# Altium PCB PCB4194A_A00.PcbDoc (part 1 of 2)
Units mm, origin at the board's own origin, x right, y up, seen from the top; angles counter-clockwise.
Board outline 30 x 45 mm, 4 copper layers (Top Layer, Signal Layer 2, Signal Layer 3, Bottom Layer), stack 1.6 mm thick; 81 components, 86 nets, 293 pads, 429 vias.
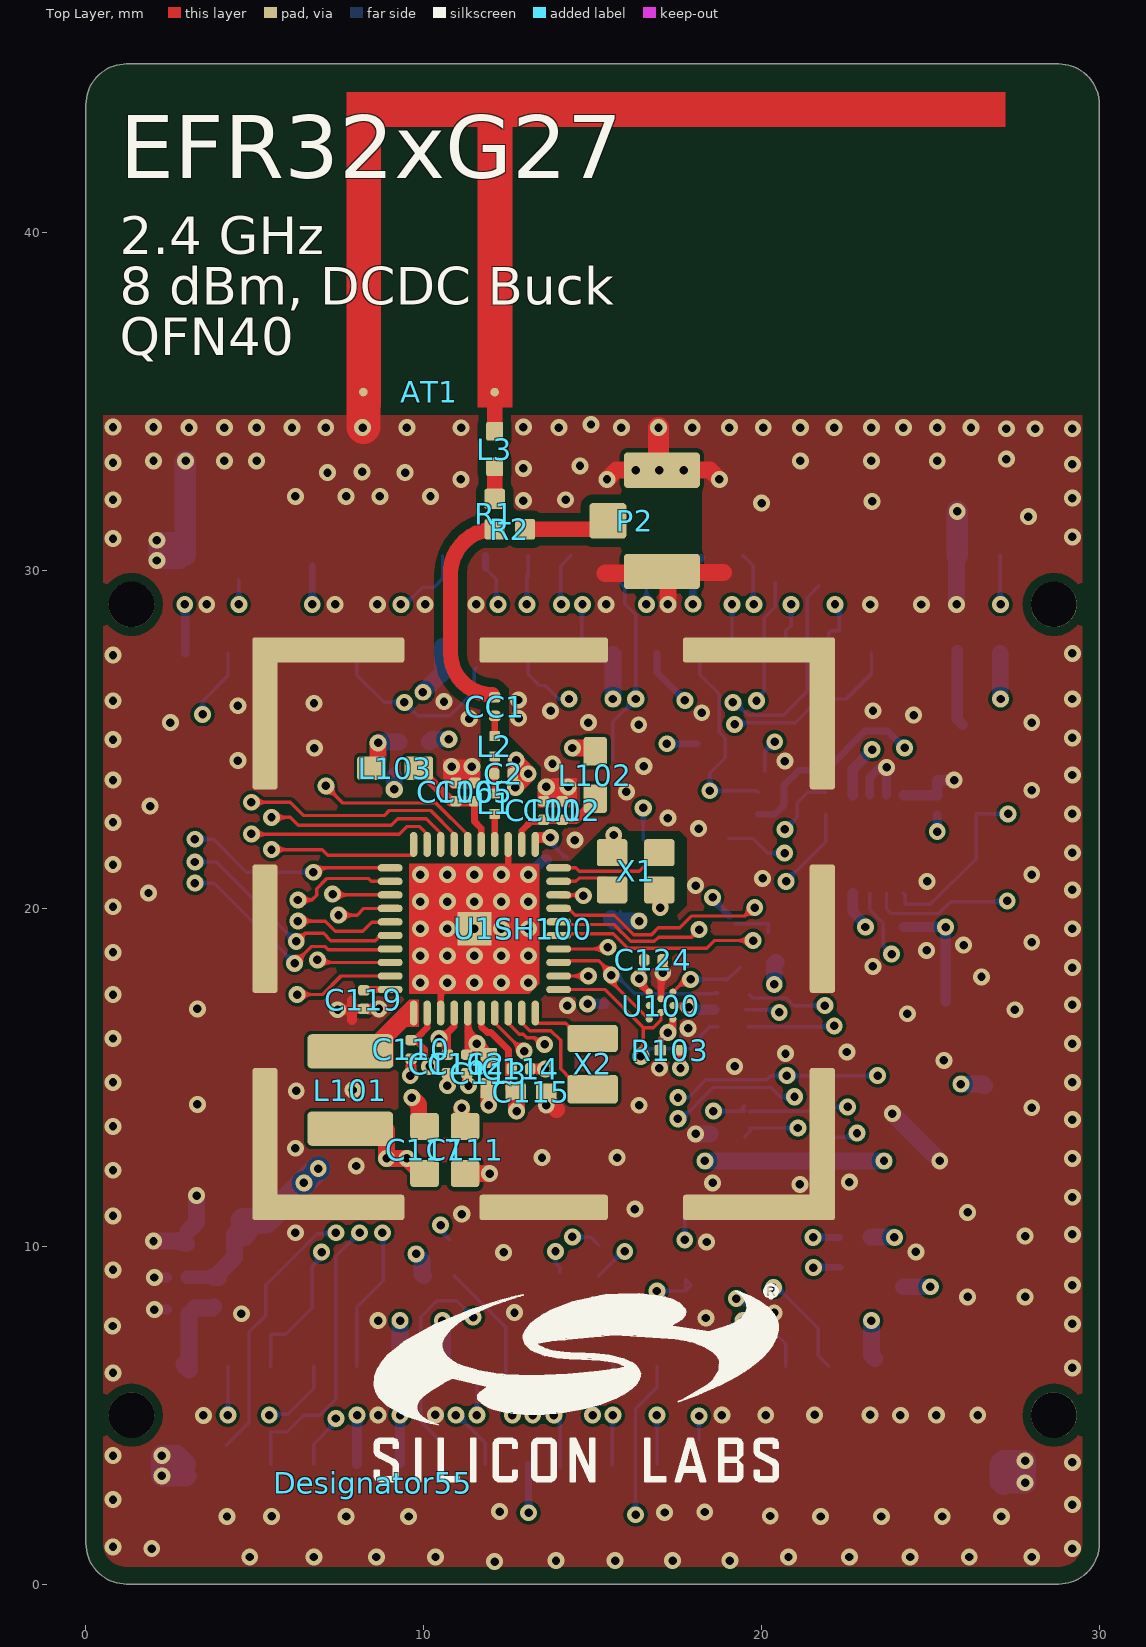
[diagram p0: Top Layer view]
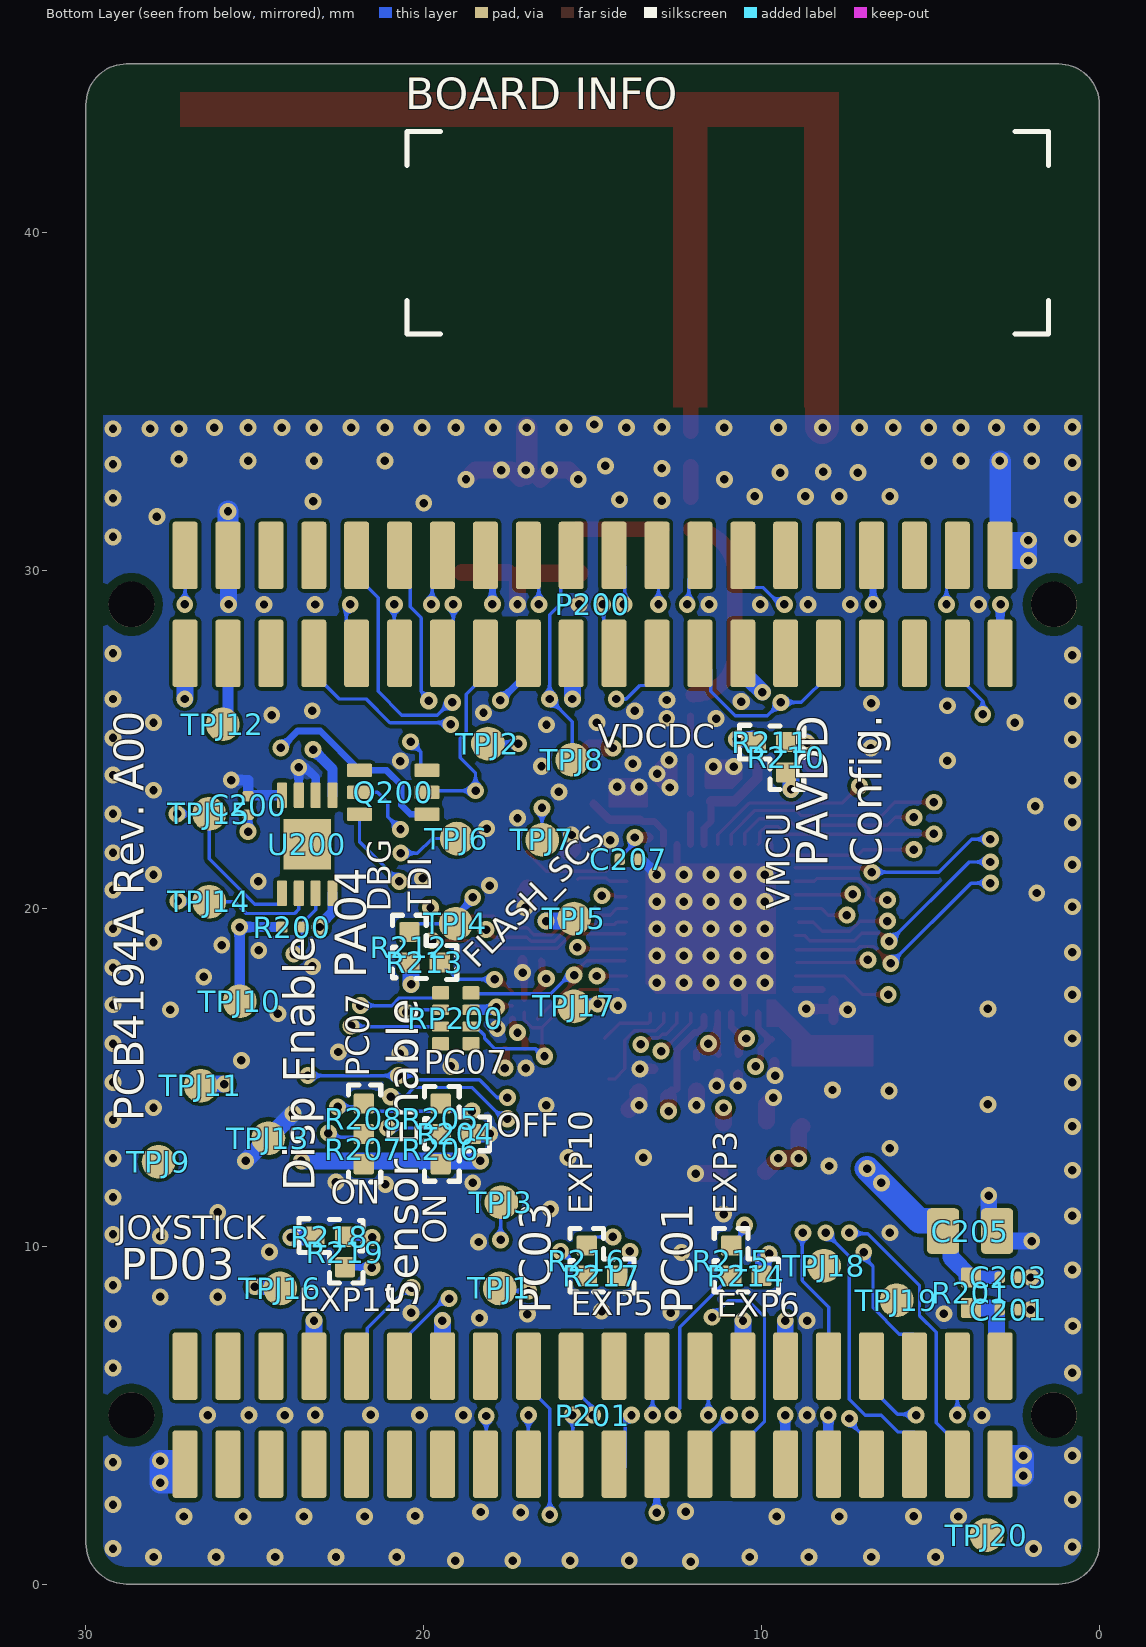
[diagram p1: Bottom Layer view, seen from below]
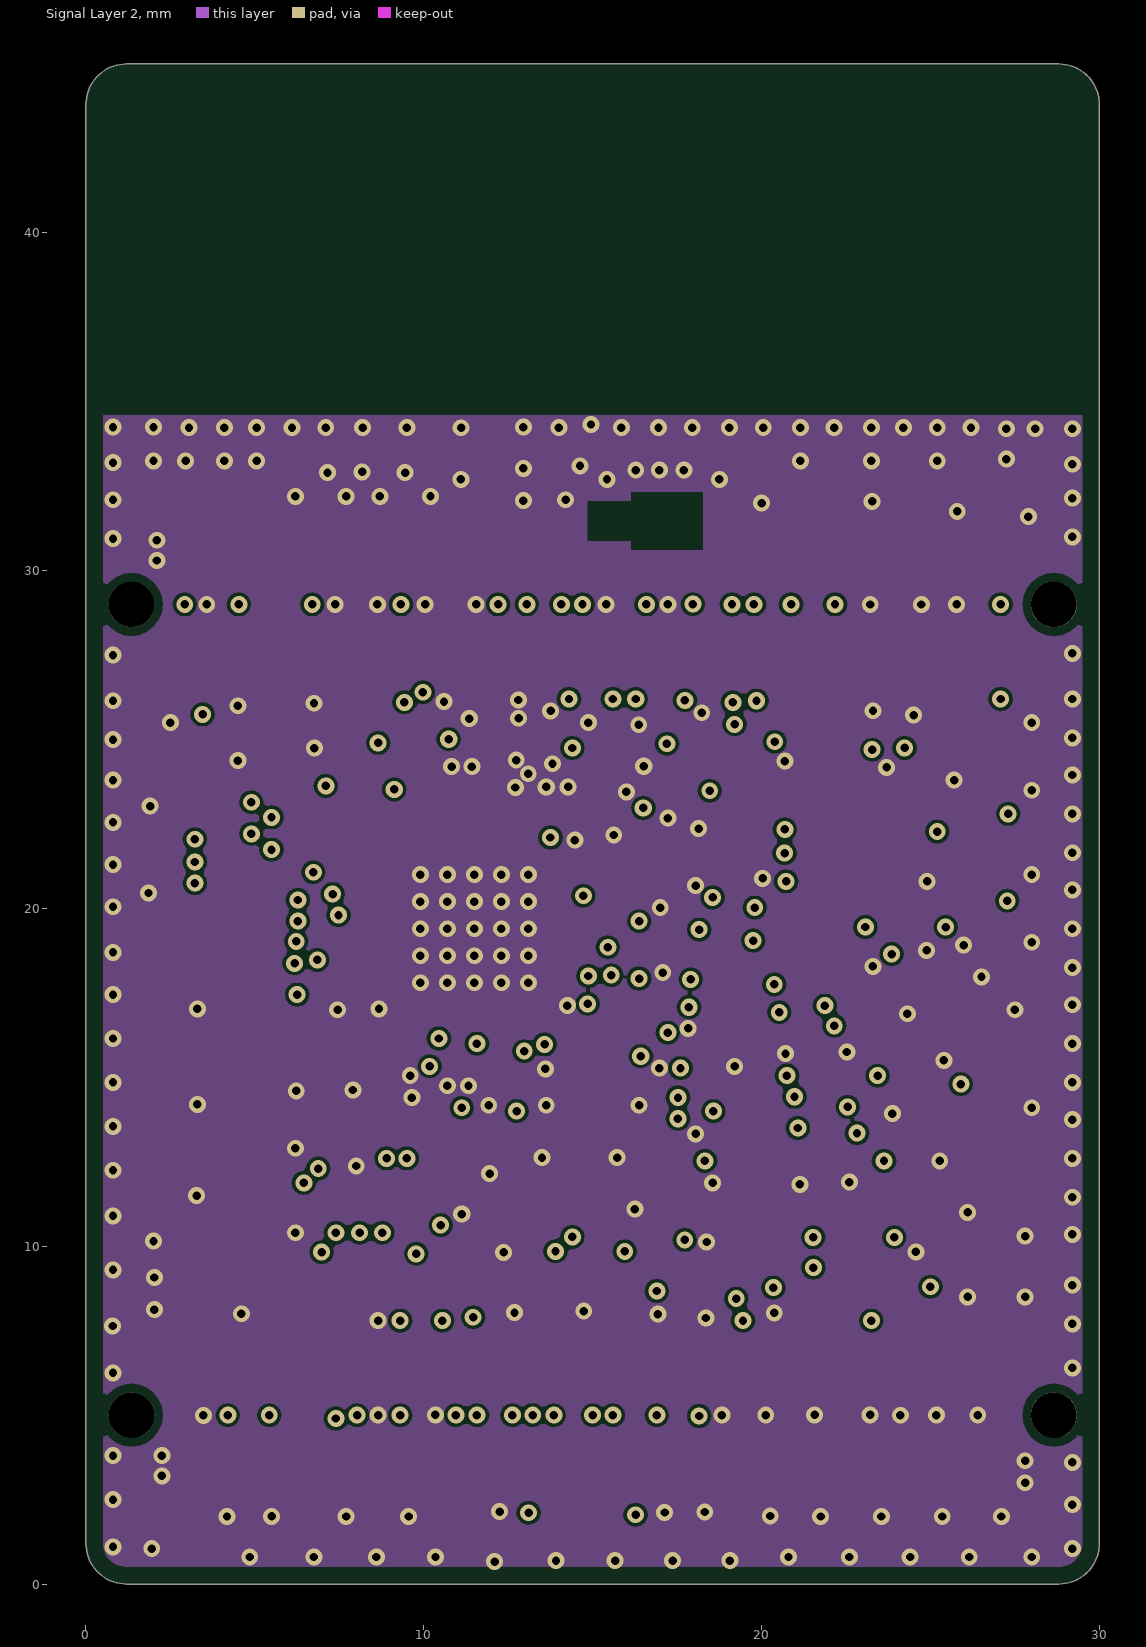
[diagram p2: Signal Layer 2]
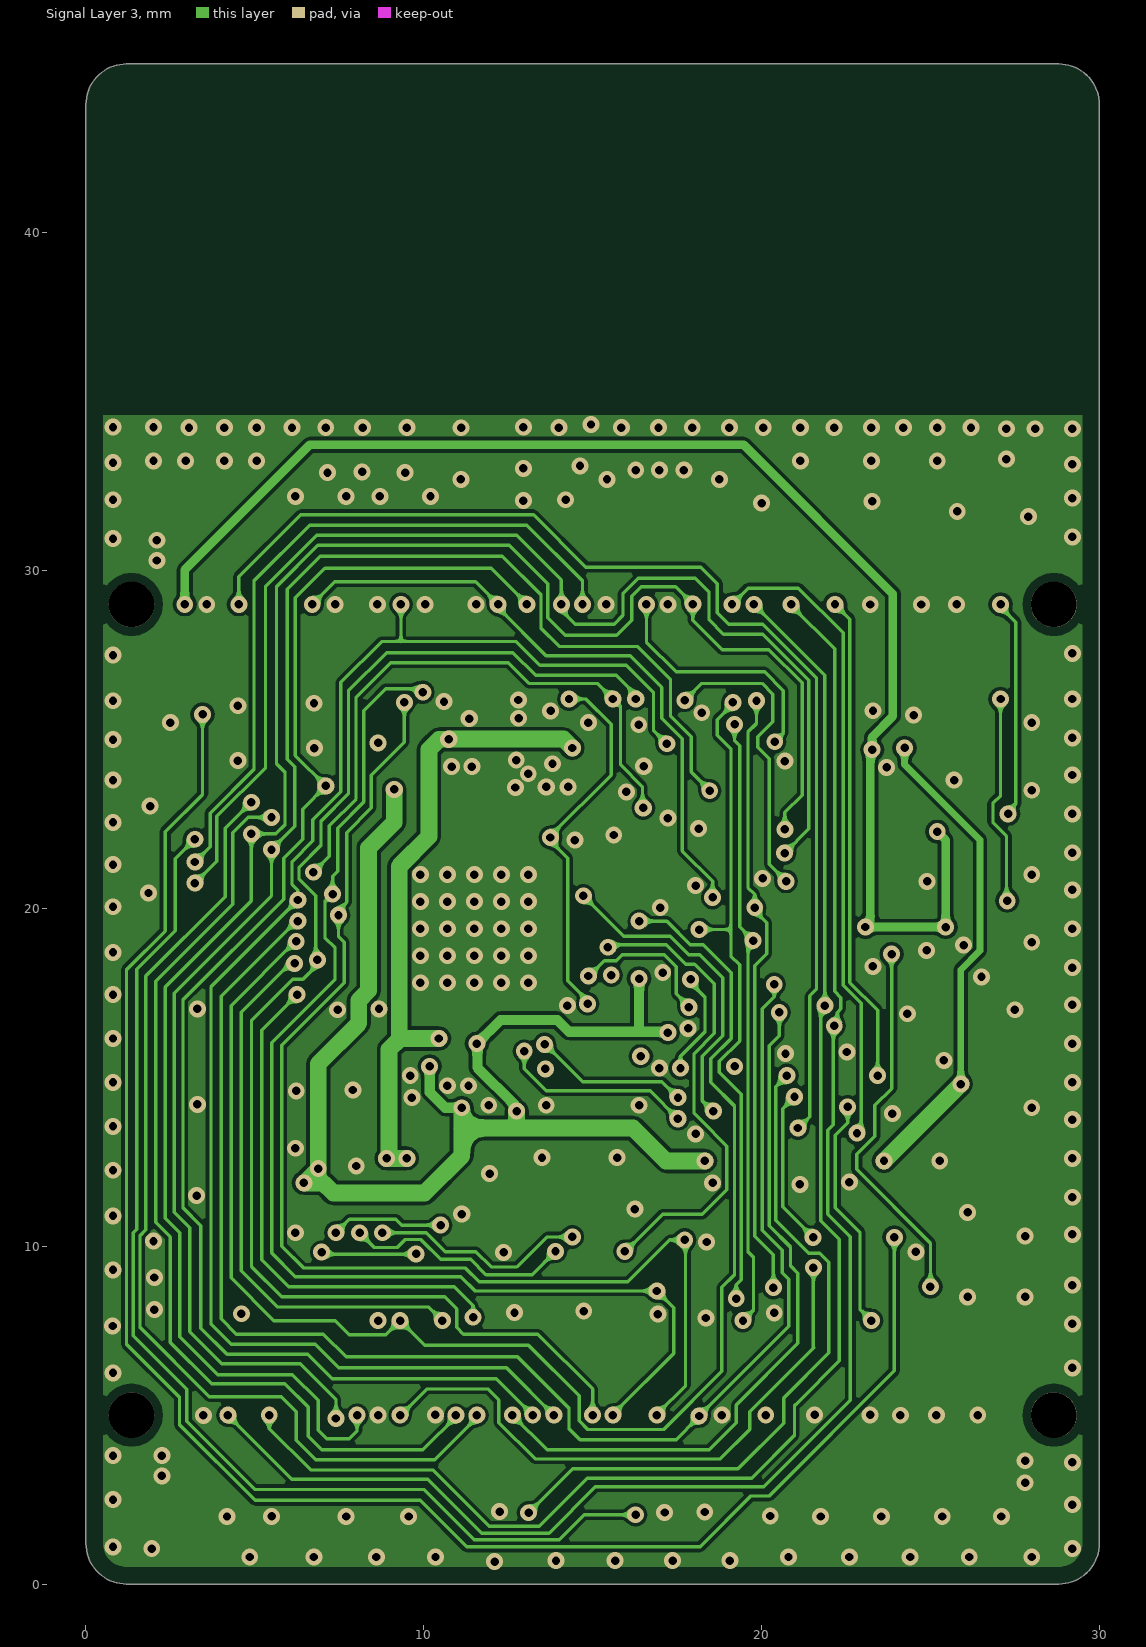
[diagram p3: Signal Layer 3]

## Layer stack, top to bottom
Top Solder: solder mask 0.0102, Solder Resist, Dk 3.5
Top Layer: signal copper 0.035
Dielectric 1: core 0.325, FR-4, Dk 4.2
Signal Layer 2: signal copper 0.018
Dielectric 3: prepreg 0.844, Dk 4.2
Signal Layer 3: signal copper 0.018
Dielectric 2: core 0.325, Dk 4.2
Bottom Layer: signal copper 0.035
Bottom Solder: solder mask 0.0102, Solder Resist, Dk 3.5

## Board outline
0,1.2 0,43.8 cw(c1.2,43.8) 1.2,45 28.8,45 cw(c28.8,43.8) 30,43.8 30,1.2 cw(c28.8,1.2) 28.8,0 1.2,0 cw(c1.2,1.2)

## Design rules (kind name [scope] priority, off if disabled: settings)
AcuteAngle [All] p1: minimum=7.00000000000000E+0001 checktracksonly=FALSE
BoardOutlineClearance [All] p1: gap=0.5
Clearance Clearance_50Ohm [InNet('50R*') vs InNet('GND')] p1: gap=0.254 except(0.15: Track-SMDPad; 0.2: SMDPad-SMDPad)
Clearance Clearance_to_Holes [InPadClass('NPTH')] p2: gap=0.254
Clearance Clerance_Polygon [InPolygon] p3: gap=0.1
Clearance Clearance_General [All] p4: gap=0.1
HoleToHoleClearance HoleToHoleClearance_ANT1toPAD [Incomponent ('ANT1') vs ISpad] p1: gap=0 allowstackedmicrovias=TRUE
HoleToHoleClearance HoleToHoleClearance_R1toR2_1 [Incomponent ('R1') vs Incomponent ('R2')] p2: gap=0 allowstackedmicrovias=TRUE
HoleToHoleClearance HoleToHoleClearance_U1toVIA_1 [InComponent ('U1') vs IsVia] p3: gap=0 allowstackedmicrovias=TRUE
HoleToHoleClearance [All] p4: gap=0.254 allowstackedmicrovias=TRUE
MinimumSolderMaskSliver [All] p1: minsoldermaskwidth=0.075
PolygonConnect Polygon_VIA_Connect [IsVia] p1: connectstyle=Direct reliefconductorwidth=0.254 reliefentries=4 polygonreliefangle="90 Angle" airgapwidth=0.254
PolygonConnect PolygonConnect_SH100 [InComponent('SH100')] p2: connectstyle=Direct reliefconductorwidth=0.254 reliefentries=4 polygonreliefangle="90 Angle" airgapwidth=0.127
PolygonConnect [All] p3: connectstyle=NoConnect reliefconductorwidth=0.254 reliefentries=4 polygonreliefangle="90 Angle" airgapwidth=0.127
RoutingVias [All] p1: holewidth=0.3 width=0.65 viastyle="Through Hole" minholewidth=0.25 minwidth=0.5 maxholewidth=1 maxwidth=1.5
ShortCircuit ShortCircuit_ANTtoPAD [InNet('NetAT1_1') vs InNet('GND')] p1: allowed=TRUE
ShortCircuit ShortCircuit_R1toR2_1 [Incomponent ('R1') vs Incomponent ('R2')] p2: allowed=TRUE
ShortCircuit [All] p3: allowed=FALSE
SilkToSilkClearance [All] p1: silktosilkclearance=0.102
SilkToSolderMaskClearance [IsPad] p1: minsilkscreentomaskgap=0.102 clearancetoexposedcopper=TRUE
SolderMaskExpansion [All] p1: expansion=0.051
Width 50ohm [InNet('50R*')] p1: maxlimit=0.457 minlimit=0.2 preferedwidth=0.457
Width [All] p2: maxlimit=5.08 minlimit=0.1 preferedwidth=0.125
25 further rules are at their usual default settings.

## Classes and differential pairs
pad class NPTH: P200-M1 P200-M2 P201-M1 P201-M2

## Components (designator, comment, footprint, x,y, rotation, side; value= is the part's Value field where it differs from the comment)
AT1 "INVERTED_F" EM358x_INVERTED_F 7.714,34.835 r0 top net-tie
C2 "1P3" C0201_L 12.361,23.983 r0 top
C101 "120P" C0201_L 13.55,22.9 r90 top
C102 "100N" C0201_L 14.1,22.9 r90 top
C105 "120P" C0201_L 11.5,23.45 r90 top
C106 "100N" C0201_L 10.95,23.45 r90 top
C110 "100N" C0201_L 9.625,15.825 r270 top
C111 "10U" C0603_L 11.225,12.85 r270 top
C112 "10N" C0201_L 11.275,15.4 r270 top
C113 "1U" C0402_L 11.925,15.125 r270 top
C114 "100N" C0201_L 12.875,15.25 r0 top
C115 "1U" C0402_L 13.175,14.575 r0 top
C116 "100N" C0201_L 10.7,15.4 r270 top
C117 "4U7" C0603_L 10.025,12.85 r90 top
C119 "1U" C0201_L 8.225,17.3 r270 top
C124 "100N" C0201_L 16.8,18.475 r0 top
C200 "100N" C0201_L 25.2,23.05 r90 bottom
C201 "100N" C0201_L 2.675,8.125 r180 bottom
C203 "100N" C0201_L 2.675,9.075 r180 bottom
C205 "10U" C0805_L 3.825,10.45 r180 bottom
C207 "100N" C0201_L 13.925,21.45 r180 bottom
CC1 "18P" C0201_L 12.103,25.973 r90 top
Designator39 "Comment" PCB_SPEC_4_LAYER -68.7,108.2 r0 top
Designator55 "Comment" LOGO_SILABS_W12.0 8.5,3 r0 top
L1 "2N7" COIL_0201_L 12.1,23.098 r90 top
L2 "3N0" COIL_0201_L 12.103,24.8 r90 top
L3 "0R" COIL_0402_L 12.1,33.6 r90 top
L101 "2U2" COIL_1008_L 7.825,14.625 r270 top
L102 "BLM18AG102SN1" COIL_MUR_BLM18_0603 15.075,23.95 r270 top
L103 "BLM18AG102SN1" COIL_MUR_BLM18_0603 9.15,24.15 r0 top
P2 "U.FL" COAX_HIROSE_U.FL_CL331-0471 17.05,31.475 r90 top
P200 "SOCKET_WCON_2X20_1.27MM_SMD" SAM_SFC-120-T2-D-A-2X20_SNUM 15,29 r0 bottom locked
P201 "SOCKET_WCON_2X20_1.27MM_SMD" SAM_SFC-120-T2-D-A-2X20_SNUM 15,5 r0 bottom locked
Q200 "BSS84" SOT-363 20.902,23.439 r0 bottom
R1 "0R" R0402_L 12.1,31.675 r90 top
R2 "0R" R0402_L 12.55,31.225 r0 top
R103 "330K" R0201_L 17.3,15.8 r180 top
R200 "10K" R0201_L 23.9,19.45 r0 bottom
R201 "0R" R0402_L 3.8,8.625 r90 bottom
R204 "0R" R0402_L 19.05,13.325 r180 bottom
R205 "0R" R0402_L 19.5,13.775 r270 bottom
R206 "0R" R0402_L 19.5,12.875 r90 bottom
R207 "0R" R0402_L 21.775,12.875 r90 bottom
R208 "0R" R0402_L 21.775,13.775 r270 bottom
R210 "0R" R0402_L 9.275,24.475 r270 bottom
R211 "0R" R0402_L 9.725,24.925 r180 bottom
R212 "0R" R0402_L 20.425,18.85 r270 bottom
R213 "0R" R0402_L 19.975,18.4 r180 bottom
R214 "0R" R0402_L 10.45,9.125 r180 bottom
R215 "0R" R0402_L 10.9,9.575 r90 bottom
R216 "0R" R0402_L 15.175,9.575 r90 bottom
R217 "0R" R0402_L 14.725,9.125 r180 bottom
R218 "0R" R0402_L 22.781,10.278 r0 bottom
R219 "0R" R0402_L 22.331,9.828 r270 bottom
RP200 "100R" RES_MNR04-8 19.05,16.75 r90 bottom
SH100 "RF_SHIELD_FRAME_BMI-S-202-F" LAIRD_BMI-S-202-F 13.55,19.4 r90 top locked
TPJ1 "TPJ_SMD" TP_1.0_SMD#1 17.75,8.75 r90 bottom locked
TPJ2 "TPJ_SMD" TP_1.0_SMD#1 18.1,24.88 r90 bottom locked
TPJ3 "TPJ_SMD" TP_1.0_SMD#1 17.7,11.3 r90 bottom locked
TPJ4 "TPJ_SMD" TP_1.0_SMD#1 19.05,19.55 r90 bottom locked
TPJ5 "TPJ_SMD" TP_1.0_SMD#1 15.55,19.7 r90 bottom locked
TPJ6 "TPJ_SMD" TP_1.0_SMD#1 19.02,22.07 r90 bottom locked
TPJ7 "TPJ_SMD" TP_1.0_SMD#1 16.49,22.03 r90 bottom locked
TPJ8 "TPJ_SMD" TP_1.0_SMD#1 15.6,24.4 r90 bottom locked
TPJ9 "TPJ_SMD" TP_1.0_SMD#1 27.85,12.5 r90 bottom locked
TPJ10 "TPJ_SMD" TP_1.0_SMD#1 25.45,17.25 r90 bottom locked
TPJ11 "TPJ_SMD" TP_1.0_SMD#1 26.6,14.75 r90 bottom locked
TPJ12 "TPJ_SMD" TP_1.0_SMD#1 25.95,25.45 r90 bottom locked
TPJ13 "TPJ_SMD" TP_1.0_SMD#1 24.6,13.2 r90 bottom locked
TPJ14 "TPJ_SMD" TP_1.0_SMD#1 26.35,20.2 r90 bottom locked
TPJ15 "TPJ_SMD" TP_1.0_SMD#1 26.35,22.8 r90 bottom locked
TPJ16 "TPJ_SMD" TP_1.0_SMD#1 24.25,8.75 r90 bottom locked
TPJ17 "TPJ_SMD" TP_1.0_SMD#1 15.55,17.1 r90 bottom locked
TPJ18 "TPJ_SMD" TP_1.0_SMD#1 8.15,9.42 r90 bottom locked
TPJ19 "TPJ_SMD" TP_1.0_SMD#2 6,8.4 r90 bottom locked
TPJ20 "TPJ_SMD" TP_1.0_SMD#1 3.34,1.45 r90 bottom locked
U1 "EFR32MG27C140F768IM40-A" QFN40_M040_5.0X5.0_EP_RP_SL 11.5,19.4 r180 top
U100 "MX25R8035F" BGA8_M040_1.24X1.75_WLCSP 17.025,17.125 r0 top
U200 "M24C02" 8-TDFN 23.45,21.9 r0 bottom locked
X1 "39.000 MHz" KDS_DSX211SH_2016 16.275,21.1 r180 top
X2 "32.768 kHz" X_MCS_CM8V-T1A 15,15.4 r270 top

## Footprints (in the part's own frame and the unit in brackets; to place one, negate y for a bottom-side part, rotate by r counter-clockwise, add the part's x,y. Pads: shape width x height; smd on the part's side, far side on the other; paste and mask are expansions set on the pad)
8-TDFN [mm] "TDFN8_M050_2.0x3.0_EP"
  rrect20% 0.3x0.75 smd mask+0.051: 1(-0.75,-1.45) 2(-0.25,-1.45) 3(0.25,-1.45) 4(0.75,-1.45) 5(0.75,1.45) 6(0.25,1.45) 7(-0.25,1.45) 8(-0.75,1.45)
  rect 1.4x1.5 smd mask+0.051: 9(0,0)
  body extent -1,-1.5 1,1.5, height 1
BGA8_M040_1.24X1.75_WLCSP [mm] "BGA, 8 pin. U100"
  round 0.21 smd mask+0.038: A1(-0.35,0.4) A3(0.35,0.4) B2(0,0.2) C1(-0.35,0) C3(0.35,0) D2(0,-0.2) E1(-0.35,-0.4) E3(0.35,-0.4)
  body extent -0.63,-0.89 0.63,0.88, height 0.52
C0201_L [mm] "Capacitor, Chip; 0.60 mm L X 0.30 mm W X 0.33 mm H body"
  rrect52% 0.31x0.34 smd: 1(-0.275,0) 2(0.275,0)
  body extent -0.3,-0.15 0.3,0.15, height 0.3
C0402_L [mm] "Chip Capacitor, 2-Leads, Body 1.0x0.5mm, IPC High Density"
  rrect20% 0.6x0.5 smd mask+0.051: 1(-0.45,0) 2(0.45,0)
  body extent -0.5,-0.25 0.5,0.25, height 0.6
C0603_L [mm] "Capacitor, 0603, High Density (C)"
  rrect25% 0.8x0.85 smd: 1(-0.7,0) 2(0.7,0)
  body extent -0.8,-0.4 0.8,0.4, height 0.95
C0805_L [mm] "Capacitor, 0805"
  rrect25% 0.95x1.35 smd: 1(-0.8,0) 2(0.8,0)
  body extent -1.1,-0.72 1.1,0.72, height 1.45
COAX_HIROSE_U.FL_CL331-0471 [mm] "COAX_HIROSE_U.FL_CL331-0471"
  rrect20% 1.05x1.1 smd mask+0.051: 1(0,1.6)
  rrect20% 1.05x2.25 smd mask+0.051: 2(-1.5,0) 3(1.5,0)
  Top Layer pour cut-out: -0.85,0.9 0.85,0.9 0.85,0.9 0.85,-1.2 -0.85,-1.2 -0.85,-1.2
  body extent -1.3,-1.55 1.3,1.3, height 0.9
COIL_0201_L [mm] "JELF243C-0021"
  rrect10% 0.3x0.3 smd: 1(-0.3,0) 2(0.3,0)
  body extent -0.32,-0.17 0.32,0.17, height 0.33
COIL_0402_L [mm] "COIL_0402_L"
  rrect20% 0.55x0.5 smd mask+0.051: 1(-0.525,0) 2(0.525,0)
  body extent -0.5,-0.25 0.5,0.25, height 0.5
COIL_1008_L [mil] "Chip Inductors, 1008 (2520), Coilcraft (190207)"
  rrect25% 40x100 smd: 1(-45,0) 2(45,0)
  body extent -58,-55 57,55, height 80
COIL_MUR_BLM18_0603 [mm] "COIL_MUR_BLM18P_0603"
  rrect25% 0.85x0.7 smd mask+0.051: 1(-0.7,0) 2(0.7,0)
  body extent -0.88,-0.48 0.87,0.48, height 0.95
EM358x_INVERTED_F [mil] "F-ANTENNA INVERSE 19.5 mm"
  round 10 smd paste-10 mask-10: 1(172.68,17.72) 2(19.68,17.85)
  Top Layer region: 0,367.2 767.72,367.2 767.72,327.07 193,327.07 193,0 153,0 153,327.07 40,327.07 40,0 20,0 0,0
KDS_DSX211SH_2016 [mm] "Copy of Silabs CE  X_KDS_DSX211SH_2.0X1.65-4"
  rrect20% 0.9x0.8 smd mask+0.051: 1(-0.7,-0.55) 2(0.7,-0.55) 3(0.7,0.55) 4(-0.7,0.55)
  body extent -1.07,-0.87 1.08,0.88, height 0.5
LAIRD_BMI-S-202-F [mm] "laired BMI-S-202-F"
  rrect20% 0.75x4.5 smd paste+0 mask+0.05: 1(-8.25,-6.375) 1(-8.25,6.375) 1(8.25,-6.375) 1(8.25,6.375)
  rrect20% 0.75x3.8 smd paste+0 mask+0.05: 1(-8.25,0) 1(8.25,0)
  rrect20% 4.5x0.75 smd paste+0 mask+0.05: 1(-6.375,8.25) 1(-6.375,-8.25) 1(6.375,8.25) 1(6.375,-8.25)
  rrect20% 3.8x0.75 smd paste+0 mask+0.05: 1(0,8.25) 1(0,-8.25)
  body extent -8.6,-8.6 8.6,8.6, height 5.5
LOGO_SILABS_W12.0 [mm] "LOGO_SILABS_W12.0 (170217)"
  silkscreen extent 0.03,0.03 11.99,5.88
PCB_SPEC_4_LAYER [mm]
QFN40_M040_5.0X5.0_EP_RP_SL [mm]
  rect 1x1 smd paste-1.95 mask+0.05: 0(0,0)
  oval 0.74x0.22 smd mask+0.05: 1(-2.495,1.8) 2(-2.495,1.4) 3(-2.495,1) 4(-2.495,0.6) 5(-2.495,0.2) 6(-2.495,-0.2) 7(-2.495,-0.6) 8(-2.495,-1) 9(-2.495,-1.4) 10(-2.495,-1.8) 21(2.495,-1.8) 22(2.495,-1.4) 23(2.495,-1) 24(2.495,-0.6) 25(2.495,-0.2) 26(2.495,0.2) 27(2.495,0.6) 28(2.495,1) 29(2.495,1.4) 30(2.495,1.8)
  oval 0.22x0.74 smd mask+0.05: 11(-1.8,-2.495) 12(-1.4,-2.495) 13(-1,-2.495) 14(-0.6,-2.495) 15(-0.2,-2.495) 16(0.2,-2.495) 17(0.6,-2.495) 18(1,-2.495) 19(1.4,-2.495) 20(1.8,-2.495) 31(1.8,2.495) 32(1.4,2.495) 33(1,2.495) 34(0.6,2.495) 35(0.2,2.495) 36(-0.2,2.495) 37(-0.6,2.495) 38(-1,2.495) 39(-1.4,2.495) 40(-1.8,2.495)
  Top Layer pour cut-out: -2.125,1.925 -2.125,-1.925 -1.925,-2.125 1.925,-2.125 2.125,-1.925 2.125,1.925 1.925,2.125 -1.925,2.125
  Top Layer region: 1.925,-1.925 -1.925,-1.925 -1.925,1.625 -1.625,1.925 1.925,1.925
  body extent -2.5,-2.5 2.5,2.5, height 1.01
R0201_L [mm] "Resistor (Chip2PinSM127P600-8N) (170921)"
  rrect25% 0.34x0.32 smd: 1(-0.3,0) 2(0.3,0)
  body extent -0.32,-0.13 0.32,0.13, height 0.3
R0402_L [mm] "Chip Resistor, 2-Leads, Body 1.0x0.5mm, IPC High Density"
  rrect20% 0.6x0.6 smd mask+0.051: 1(-0.45,0) 2(0.45,0)
  body extent -0.5,-0.25 0.5,0.25, height 0.6
RES_MNR04-8 [mm] "Chip resistor network 8pin"
  rrect20% 0.4x0.5 smd mask+0.051: 1(-0.75,-0.45) 4(0.75,-0.45) 5(0.75,0.45) 8(-0.75,0.45)
  rrect20% 0.3x0.5 smd mask+0.051: 2(-0.25,-0.45) 3(0.25,-0.45) 6(0.25,0.45) 7(-0.25,0.45)
  body extent -1,-0.4 1,0.4, height 0.5
SAM_SFC-120-T2-D-A-2X20_SNUM [mm]
  rrect20% 0.74x2 smd mask+0.05: 1(-12.065,1.45) 2(-12.065,-1.45) 3(-10.795,1.45) 4(-10.795,-1.45) 5(-9.525,1.45) 6(-9.525,-1.45) 7(-8.255,1.45) 8(-8.255,-1.45) 9(-6.985,1.45) 10(-6.985,-1.45) 11(-5.715,1.45) 12(-5.715,-1.45) 13(-4.445,1.45) 14(-4.445,-1.45) 15(-3.175,1.45) 16(-3.175,-1.45) 17(-1.905,1.45) 18(-1.905,-1.45) 19(-0.635,1.45) 20(-0.635,-1.45) 21(0.635,1.45) 22(0.635,-1.45) 23(1.905,1.45) 24(1.905,-1.45) 25(3.175,1.45) 26(3.175,-1.45) 27(4.445,1.45) 28(4.445,-1.45) 29(5.715,1.45) 30(5.715,-1.45) 31(6.985,1.45) 32(6.985,-1.45) 33(8.255,1.45) 34(8.255,-1.45) 35(9.525,1.45) 36(9.525,-1.45) 37(10.795,1.45) 38(10.795,-1.45) 39(12.065,1.45) 40(12.065,-1.45)
  round 1.35 hole 1.35 unplated paste-5.563 mask-5.563: M1(13.652,0) M2(-13.652,0)
  body extent -14.65,-1.58 14.65,2.25, height 4.57
SOT-363 [mm] "SOT363 IPC L"
  rrect25% 0.75x0.4 smd: 1(-1,0.65) 2(-1,0) 3(-1,-0.65) 4(1,-0.65) 5(1,0) 6(1,0.65)
  body extent -1.15,-1.05 1.15,1.05, height 1
TP_1.0_SMD#1 [mm] "Test Point, 1.0 mm, SMD"
  round 1 smd paste-0.501: 1(0,0)
  body extent -0.2,-0.2 0.2,0.2, height 0.01
TP_1.0_SMD#2 [mm] "Test Point, 1.0 mm, SMD"
  round 1 smd paste-0.501 mask-1: 1(0,0)
  body extent -0.2,-0.2 0.2,0.2, height 0.01
X_MCS_CM8V-T1A [mm] "Crystal MCS CM8V-T1A (2 pin)"
  rrect25% 0.8x1.5 smd mask+0.051: 1(-0.75,0)
  rrect25% 0.85x1.5 smd mask+0.051: 2(0.75,0)
  body extent -1,-0.6 1,0.6, height 0.95

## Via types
v1: diameter 0.5, hole 0.25, Top Layer to Bottom Layer, tented both sides, 401 vias
v2: diameter 0.508, hole 0.25, Top Layer to Bottom Layer, tented both sides, 28 vias

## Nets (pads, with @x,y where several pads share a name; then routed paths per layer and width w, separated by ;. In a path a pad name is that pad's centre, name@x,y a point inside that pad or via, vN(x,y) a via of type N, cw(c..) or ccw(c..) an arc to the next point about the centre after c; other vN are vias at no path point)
3V3: C200.1 P200.1 R200.2 TPJ10.1 U200.1 U200.8 | length 49.4
  Signal Layer 3 w0.254: v1(2.925,29) 2.925,30.025 6.627,33.727 19.473,33.727 23.887,29.313 23.887,25.687 23.275,25.075 v1(23.275,24.7) 23.223,24.648 23.223,19.648 v1@23.075,19.5 ; v1(23.075,19.45) v1@23.075,19.5 ; v1(25.2,22.275) 25.45,22.025 v1(25.45,19.45) 22.975,19.45 23.05,19.525 v1@23.075,19.5
  Bottom Layer w0.254: v1(2.925,29) 2.95,29 2.975,28.975 2.935,28.935 P200.1@2.935,27.55 ; v1(25.2,22.275) C200.1@25.2,22.775
  Bottom Layer w0.305: U200.8@22.7,20.45 22.7,19.9 23.075,19.525 v1(23.075,19.45) ; U200.1@22.7,23.35 22.7,24.125 v1(23.275,24.7) ; R200.2@24.2,19.45 25.35,19.45 25.45,19.35 v1(25.45,19.45) TPJ10.1@25.45,17.25
5V: P200.37 TPJ12.1 | length 2.2
  Bottom Layer w0.33: P200.37@25.795,27.635 P200.37@25.795,27.55 25.795,25.605 TPJ12.1@25.95,25.45
50R_IFA: AT1.1 L3.2 | length 1.2
  Top Layer w0.457: L3.2@12.1,34.125 AT1.1@12.1,35.285
50R_LANT2: L3.1 R1.2 | length 0.9
  Top Layer w0.457: R1.2@12.1,32.175 L3.1@12.1,33.075
50R_P2: P2.1 R2.2 | length 2.5
  Top Layer w0.457: R2.2@12.95,31.225 P2.1@15.475,31.225
50R_R1: CC1.2 R1.1 R2.1 | length 6.3
  Top Layer w0.457: CC1.2@12.022,26.329 cw(c12.022,27.56) 10.791,27.56 10.791,29.917 cw(c12.1,29.917) R1.1@12.1,31.225
BOARD_ID_SCL: P200.39 TPJ14.1 U200.6 | length 12.1
  Signal Layer 3 w0.1: v1(27.075,26.2) 27.075,23.341 26.85,23.116 26.85,22.545 27.25,22.145 27.25,20.275 27.2,20.225 v1(27.275,20.225)
  Bottom Layer w0.1: U200.6@23.7,20.45 23.7,19.975 23.825,19.85 25.25,19.85 25.6,20.2 TPJ14.1@26.35,20.2 27.375,20.2 27.35,20.225 v1(27.275,20.225)
  Bottom Layer w0.5: P200.39@27.065,27.55 27.065,26.21 v1(27.075,26.2)
BOARD_ID_SDA: P200.40 TPJ15.1 U200.5 | length 13.3
  Signal Layer 3 w0.102: v1(27.075,29) 27.075,28.925 27.526,28.474 27.526,23.101 27.3,22.875 v1(27.3,22.8)
  Bottom Layer w0.102: U200.5@24.2,20.45 24.25,20.4 24.25,20.125 25,20.125 26.35,21.475 TPJ15.1@26.35,22.8 v1(27.3,22.8) ; P200.40@27.065,30.45 v1@27.065,29 ; v1(27.075,29) v1@27.065,29 ; v1@27.065,29 27.065,28.965 27.03,29 v1@27.065,29
BOARD_ID_WP: R200.1 TPJ16.1 U200.7 | length 14.1
  Signal Layer 3 w0.1: v1(23.85,18.65) 23.85,14.669 23.352,14.171 23.352,13.258 22.815,12.721 22.815,12.281 25,10.096 v1(25,8.8)
  Bottom Layer w0.1: U200.7@23.2,20.45 23.2,19.966 23.6,19.566 R200.1@23.6,19.45 23.6,18.9 v1(23.85,18.65) ; TPJ16.1@24.2,8.8 TPJ16.1@24.25,8.75
  Bottom Layer w0.5: TPJ16.1@24.2,8.8 v1(25,8.8)
EFR32_#RESET: C207.1 P200.17 TPJ17.1 U1.11 | length 14.8
  Top Layer w0.3: U1.11@13.35,22.101 v2(13.751,22.101)
  Signal Layer 3 w0.1: v2@13.725,22.025 14.262,21.488 14.262,17.863 14.875,17.25 v1@14.875,17.2 ; v2(13.751,22.101) 13.751,22.151 15.55,23.95 15.55,25.45 14.8,26.2 v1(14.3,26.2)
  Bottom Layer w0.1: P200.17@13.095,27.55 13.095,26.93 13.425,26.6 13.6,26.6 14,26.2 v1(14.3,26.2) ; v2@13.725,22.075 13.725,21.975 14.163,21.538 C207.1@14.138,21.512 ; C207.1@14.188,21.562 C207.1@14.25,21.5
  Bottom Layer w0.3: v1(14.851,17.176) TPJ17.1@15.354,17.176
EFR32_PA00: P200.21 P201.24 TPJ7.1 U1.21 | length 64.6
  Top Layer w0.1: v1(6.732,21.07) 6.701,21.101 6.8,21.2 6.85,21.2 U1.21@9.005,21.2
  Signal Layer 3 w0.1: v1@3.425,22.05 v1(3.225,22.05) 2.642,21.467 2.642,19.342 1.5,18.2 1.5,10.499 1.4,10.399 1.4,7.35 2.981,5.769 2.981,4.813 4.994,2.8 10,2.8 11.491,1.309 14.009,1.309 14.75,2.05 v1(16.27,2.05) ; v1(6.732,21.07) 7.206,21.545 7.206,22.449 7.995,23.239 7.995,26.249 9.019,27.272 12.503,27.272 13.115,26.66 15.14,26.66 v2(15.6,26.2) 15.826,25.974 15.826,24.249 16.475,23.6 v2@16.475,23.075
  Bottom Layer w0.1: v1@3.425,22.05 3.776,22.05 4.751,21.075 6.727,21.075 v1(6.732,21.07) ; P200.21@15.6,27.515 P200.21@15.635,27.55 ; v1(16.27,2.05) 16.27,5.19 16.905,5.825 P201.24@16.905,6.45 ; TPJ7.1@16.49,22.03 16.5,22.04 v2(16.5,22.975)
  Bottom Layer w0.5: v2(15.6,26.2) P200.21@15.6,27.515
EFR32_PA01: P200.14 P201.19 TPJ2.1 U1.22 | length 52.9
  Top Layer w0.1: v1(6.275,20.25) 6.69,20.25 6.828,20.388 6.828,20.579 7.136,20.888 8.354,20.888 8.441,20.8 U1.22@9.005,20.8
  Signal Layer 3 w0.1: v1(9.325,29) 9.325,27.902 ; v1(13.85,5) 12.45,6.4 7.484,6.4 6.784,7.1 4.3,7.1 3.7,7.7 3.7,17.675 v1(6.275,20.25) 6.275,20.341 6.275,20.534 6.1,20.708 6.1,21.388 6.713,22.001 6.713,22.623 7.547,23.457 7.547,26.697 8.752,27.902 9.325,27.902 ; v1(17.2,24.875) 16.8,25.275 16.8,26.4 16,27.2 13.44,27.2 12.738,27.902 9.325,27.902
  Bottom Layer w0.1: v1@9.325,29.025 9.475,29.025 9.95,29.5 10.3,29.5 10.555,29.755 P200.14@10.555,30.45 ; P201.19@14.04,3.45 v1@14.04,4.91
  Bottom Layer w0.2: v1(17.2,24.875) TPJ2.1@18.1,24.875
EFR32_PA02: P200.13 P201.21 TPJ1.1 U1.23 | length 42.4
  Top Layer w0.1: v1@7.275,20.4 U1.23@9.005,20.4
  Signal Layer 3 w0.1: v1@7.25,20.376 7.075,20.201 7.075,19.132 7.373,18.834 7.373,17.898 5.5,16.025 5.5,9.8 6.2,9.1 11.097,9.1 11.522,8.675 v1(16.9,8.675) 17.4,8.175 17.4,6.825 15.675,5.1 15.688,5.088 15.776,5 v1(15.6,5) ; v1(7.3,20.426) 7.3,20.951 7.454,21.105 7.454,22.379 8.226,23.151 8.226,25.851 8.876,26.501 9.876,26.501 v1(9.975,26.401)
  Bottom Layer w0.1: P201.21@15.585,3.525 v1@15.585,4.91 ; v1(16.9,8.675) 17.75,8.675 17.925,8.85 17.75,9.025 TPJ1.1@17.75,8.75
  Bottom Layer w0.5: v1(9.975,26.401) 9.975,26.405 10.35,26.779 10.353,26.779 10.55,26.976 P200.13@10.55,27.75
EFR32_PA03: P200.9 P200.15 P201.23 TPJ3.1 U1.24 | length 45.7
  Top Layer w0.1: v1(7.475,19.801) 8.026,19.801 8.225,20 U1.24@9.005,20
  Signal Layer 3 w0.1: v1(7.475,19.801) 7.475,19.173 7.65,18.998 7.65,17.8 5.8,15.95 5.8,10 6.444,9.356 11.227,9.356 11.636,8.946 16.044,8.946 17.284,10.187 v1(17.725,10.187) 17.725,10.162 17.75,10.137 17.75,5.875 v1@16.925,5.05 ; v1@7.479,19.947 7.722,20.19 7.722,22.247 8.451,22.976 8.451,23.949 9.425,24.924 v1(9.425,26.101)
  Bottom Layer w0.1: P200.9@8.015,27.55 8.015,26.91 8.824,26.101 v1(9.425,26.101) 9.501,26.101 v1@9.463,26.063 ; v1@9.462,26.063 9.825,25.7 10.775,25.7 11.5,26.425 11.5,27.075 P200.15@11.55,27.125 ; P201.23@16.905,3.55 v1@16.905,5.02 ; TPJ3.1@17.7,11.3 17.725,11.275 v1@17.725,10.425
  other v1: 16.9,5
EFR32_PA04: P201.25 R212.2 R213.1 U1.25 | length 48
  Top Layer w0.1: v1@6.341,19.625 7.086,19.625 7.386,19.325 8.2,19.325 8.466,19.591 U1.25@8.898,19.591
  Signal Layer 3 w0.1: v1(6.275,19.626) 6.226,19.626 4,17.4 4,7.85 4.45,7.4 7.026,7.4 7.701,6.725 12.775,6.725 14.3,5.2 14.3,4.6 14.625,4.275 17.475,4.275 18.088,4.888 18.15,4.825 v1(18.15,4.975) 18.175,4.975 18.162,4.987 20.8,7.625 20.8,9.025 20.61,9.215 20.61,9.886 20.022,10.474 20.022,17.035 20.375,17.388 v1(20.375,17.75)
  Bottom Layer w0.1: P201.25@18.15,4.275 v1(18.15,4.975) ; v1@20.288,17.837 20.201,17.751 v1(20.375,17.75)
  Bottom Layer w0.5: v1(20.375,17.75) 20.375,18.35 R212.2@20.425,18.4
EFR32_PA05: P200.19 P201.12 TPJ5.1 U1.26 | length 76.4
  Top Layer w0.102: v1@6.225,19 6.491,19.266 7.034,19.266 7.25,19.05 8.568,19.05 8.718,19.2 U1.26@9.005,19.2
  Signal Layer 3 w0.102: v1(3.225,21.375) 3.674,21.824 3.674,22.824 4.975,24.125 4.975,29.704 6.621,31.35 13.05,31.35 14.7,29.7 v1(14.7,29) ; v1(6.225,19.026) 6.201,19.026 4.3,17.125 4.3,9.064 5.564,7.8 7.375,7.8 7.8,7.375 8.875,7.375 v1(9.3,7.8) 10.025,7.075 13.1,7.075 14.599,5.576 14.599,4.834 14.858,4.575 17.1,4.575 18.825,6.3 18.825,8.781 19.198,9.154 19.198,14.152 18.5,14.85 18.5,15.55 19.1,16.15 19.1,18.1 18.27,18.93 17.895,18.93 17.201,19.624 v1(16.378,19.624)
  Bottom Layer w0.102: v1@3.425,21.375 3.851,21.375 6.2,19.026 v1(6.225,19.026) ; P200.19@14.365,27.55 14.675,27.55 14.675,28.975 v1(14.7,29) ; TPJ5.1@15.825,19.7 TPJ5.1@15.825,19.925
  Bottom Layer w0.5: P201.12@9.285,6.45 9.3,6.465 v1(9.3,7.8) ; TPJ5.1@15.55,19.7 15.626,19.624 v1(16.378,19.624)
EFR32_PA06: P200.20 P201.14 TPJ6.1 U1.27 | length 65.2
  Top Layer w0.1: v1(6.175,18.375) 6.184,18.375 6.684,18.875 7.075,18.875 7.176,18.774 U1.27@8.979,18.774
  Signal Layer 3 w0.1: v1(3.225,20.75) 3.875,21.4 3.875,22.724 5.316,24.165 5.316,29.535 6.831,31.05 12.75,31.05 14.075,29.725 v1(14.075,29) ; v1@6.225,18.331 6.181,18.375 v1(6.175,18.375) 6.05,18.375 4.6,16.925 4.6,9.271 5.671,8.2 10.15,8.2 v1(10.55,7.8) ; v1@14.125,28.95 14.125,28.775 14.482,28.418 15.643,28.418 15.898,28.673 15.898,29.323 16.35,29.775 18.032,29.775 18.445,29.362 18.445,28.55 18.872,28.123 20.038,28.123 21.4,26.761 21.4,22.356 v1(20.681,21.637)
  Bottom Layer w0.1: v1@3.425,20.75 3.8,20.75 v1(6.175,18.375) v1@6.238,18.312 ; v1(10.55,7.8) 10.555,7.795 P201.14@10.555,6.45 ; v1@14.05,29.225 14.05,30.135 P200.20@14.365,30.45 ; TPJ6.1@19.02,22.07 19.753,22.07 20.186,21.637 v1(20.681,21.637)
  Bottom Layer w0.5: v1(10.55,7.8) 10.55,6.455 P201.14@10.555,6.45
EFR32_PA07: P200.22 P201.22 TPJ8.1 U1.28 | length 50.8
  Top Layer w0.1: v1(6.85,18.475) 6.925,18.4 U1.28@8.953,18.4
  Signal Layer 3 w0.1: v1@6.8,18.475 6.8,20.371 6.308,20.863 6.308,21.222 6.958,21.871 6.958,22.585 7.771,23.399 7.771,26.44 8.906,27.575 12.638,27.575 13.313,26.9 15.7,26.9 16.275,26.325 v2(16.275,26.2) ; v1@6.85,18.325 6.425,17.9 6.125,17.9 4.9,16.675 4.9,9.4 5.8,8.5 10.617,8.5 10.974,8.143 10.974,7.602 11.176,7.4 13.375,7.4 15,5.775 v1(15,5)
  Bottom Layer w0.1: v1(15,5) 15,5.224 15.635,5.859 P201.22@15.635,6.45 P201.22@15.435,6.65 ; TPJ8.1@15.6,24.4 15.6,25.525 v2(16.275,26.2) 16.275,28.7 15.95,29.025 15.95,29.5 P200.22@15.8,29.65
EFR32_PA08: P201.13 U1.29 | length 25
  Top Layer w0.1: v1(6.25,17.451) 7.001,17.451 7.55,18 U1.29@9.005,18
  Signal Layer 3 w0.1: v1@6.101,17.301 5.2,16.4 5.2,9.6 6,8.8 10.906,8.8 11.464,8.242 v1(11.464,7.898) ; v1@6.25,17.475 v1@6.375,17.6
  Bottom Layer w0.1: P201.13@10.555,3.55 10.555,4.174 9.911,4.818 9.911,7.901 10.391,8.381 10.98,8.381 v1(11.464,7.898)
EFR32_PB00: P200.25 P201.7 Q200.2 U1.20 | length 59.5
  Top Layer w0.1: v1(5.492,21.742) 6.991,21.742 7.157,21.575 9.7,21.575 U1.20@9.7,21.895 ; U1.20@9.725,21.875 U1.20@9.725,22.05
  Signal Layer 3 w0.1: v1(7.4,4.9) 7.4,5.475 6.35,6.525 4.025,6.525 3.075,7.475 3.075,10.55 2.618,11.007 2.618,17.493 5.492,20.367 v1(5.492,21.742) 6.179,22.429 6.179,24.191 5.957,24.413 5.957,29.452 6.93,30.425 12.329,30.425 13.471,29.283 13.471,28.296 14.011,27.756 16.324,27.756 17.306,26.774 17.306,25.695 17.919,25.083 17.919,24.04 18.467,23.491 v1(18.467,23.484)
  Bottom Layer w0.1: P201.7@6.745,3.55 6.745,4.145 7.4,4.8 v1(7.4,4.9) ; P200.25@18.175,27.55 18.175,26.919 18.746,26.348 18.746,25.213 18.92,25.039 18.92,24.46 18.467,24.007 v1(18.467,23.484) 19.857,23.484 Q200.2@19.902,23.439
EFR32_PB01: P200.26 P201.9 Q200.5 U1.19 | length 67.4
  Top Layer w0.1: v1(4.896,22.209) 4.909,22.196 9.271,22.196 9.5,22.425 9.875,22.425 10.05,22.25 10.05,21.945 U1.19@10.1,21.895
  Signal Layer 3 w0.1: v1(8.025,5) 8.025,4.533 7.792,4.3 7.125,4.3 6.875,4.55 6.875,5.437 6.112,6.2 3.9,6.2 2.775,7.325 2.775,10.4 2.35,10.825 2.35,17.675 4.896,20.221 v1(4.896,22.209) 5.622,22.209 5.892,22.48 5.892,24.039 5.641,24.29 5.641,29.523 6.868,30.75 12.53,30.75 13.671,29.609 13.671,28.605 14.19,28.086 15.707,28.086 16.152,28.531 16.152,29.238 16.436,29.521 17.454,29.521 v1(17.967,29.009) 17.967,28.527 18.832,27.662 20.216,27.662 21.2,26.678 21.2,23.352 20.689,22.841 v1(20.689,22.338)
  Bottom Layer w0.1: P201.9@8.015,3.55 P201.9@8.025,3.56 ; v1@8.015,5 v1(8.025,5) ; P200.26@18.175,30.45 P200.26@18.237,30.388 ; v1(20.689,22.338) 21.062,22.711 21.062,23.131 21.37,23.439 Q200.5@21.902,23.439
  Bottom Layer w0.2: v1(17.967,29.009) 17.967,30.119 P200.26@18.237,30.388
  Bottom Layer w0.3: P201.9@8.025,3.56 v1(8.025,5)
EFR32_PB02: P201.15 U1.18 | length 35.8
  Top Layer w0.1: v1@5.492,22.596 5.592,22.696 6.048,22.696 6.281,22.462 9.037,22.462 9.225,22.65 10.075,22.65 10.5,22.225 U1.18@10.5,21.895
  Signal Layer 3 w0.1: v1(5.492,22.696) 4.8,22.696 4.346,22.242 4.346,20.121 2.069,17.844 2.069,10.706 2.5,10.275 2.5,7.15 3.725,5.925 5.891,5.925 6.575,5.241 6.575,4.375 6.975,3.975 9.975,3.975 v1@11,5
  Bottom Layer w0.1: v1@11,5 11.825,4.175 P201.15@11.825,3.55
  other v1: 10.95,5
EFR32_PB03: P201.16 U1.17 | length 37.5
  Top Layer w0.1: v1@4.896,23.044 4.996,23.144 6.052,23.144 6.446,22.75 8.825,22.75 8.975,22.9 10.201,22.9 10.9,22.201 U1.17@10.9,21.895
  Signal Layer 3 w0.1: v1(4.896,23.144) 4.121,22.37 4.121,20.346 1.775,18 1.775,10.491 1.6,10.316 1.6,7.6 3.65,5.55 5.778,5.55 6.225,5.103 6.225,4.25 6.8,3.675 10.325,3.675 v1@11.575,4.925
  Bottom Layer w0.1: v1@11.575,5.05 P201.16@11.575,6.125
  other v1: 11.575,5
EFR32_PB04: P200.18 P201.18 U1.16 | length 50.2
  Top Layer w0.1: v1@6.9,23.626 v1(7.1,23.626) 7.604,23.122 10.359,23.122 11.3,22.181 U1.16@11.3,21.895
  Signal Layer 3 w0.1: v1@12.962,29.113 12,30.075 7.075,30.075 6.2,29.2 6.2,24.526 v1(7.1,23.626) 6.416,22.942 6.416,22.05 5.85,21.484 5.85,20.275 2.873,17.298 2.873,11.14 3.4,10.613 3.4,7.575 4.175,6.8 6.563,6.8 7.288,6.075 12.151,6.075 v1(13.226,5) ; v1@13.413,4.963 v1@13.413,5
  Bottom Layer w0.1: v1@13.05,29.001 13.05,29.875 13.095,29.83 P200.18@13.095,30.45 ; v1(13.226,5) P201.18@13.226,5.973
  other v1: 13.051,29.001
EFR32_PC00: RP200.2 U1.1 U100.D2 | length 6.9
  Top Layer w0.1: U1.1@14.25,17.6 14.255,17.595 14.259,17.6 15.375,17.6 16.505,16.47 16.789,16.47 17.025,16.706 U100.D2@17.025,16.925 ; v2@16.5,15.8 16.5,16.47
  Bottom Layer w0.1: v2@16.475,15.625 16.7,15.85 17.9,15.85 18.2,16.15 18.2,16.239 18.461,16.5 RP200.2@18.6,16.5 RP200.2@18.7,16.5
  other v2: 16.426,15.626
EFR32_PC01: RP200.3 U1.2 U100.C3 | length 6.6
  Top Layer w0.1: U1.2@13.995,18 v1@14.625,18 ; U100.C3@17.375,17.125 v2@17.892,17.125
  Signal Layer 3 w0.1: v1(14.875,18) 14.8,18 14.85,17.95 15.35,18.45 15.7,18.45 15.875,18.625 17.125,18.625 17.475,18.275 17.475,17.477 17.851,17.101 v2(17.851,17.076)
  Bottom Layer w0.1: RP200.3@18.6,17 RP200.3@18.7,17
  Bottom Layer w0.3: v2@17.85,17.1 17.95,17 RP200.3@18.6,17
EFR32_PC02: RP200.4 U1.3 U100.E1 | length 7.1
  Top Layer w0.1: U1.3@14.045,18.45 15.175,18.45 v1@15.612,18.013 ; v1@15.451,18.026 15.4,17.975 16.625,16.75 U100.E1@16.625,16.725 ; v1@15.452,18.025 v1(15.55,18.025)
  Bottom Layer w0.1: v1(15.55,18.025) v1@15.698,18.025 ; v1@15.699,18.026 16.245,17.48 18.58,17.48 RP200.4@18.6,17.5 18.676,17.5 18.676,17.476 RP200.4@18.7,17.5
EFR32_PC03: R216.1 R217.1 U1.4 | length 16.9
  Top Layer w0.1: U1.4@13.995,18.8 15.4,18.8 v1(15.45,18.85)
  Signal Layer 3 w0.1: v1(15.45,18.85) 15.525,18.925 17.175,18.925 17.749,18.351 18.017,18.351 18.6,17.767 18.6,16.3 18.001,15.701 18.001,13.935 18.211,13.725 18.216,13.725 18.975,12.966 18.975,11.675 18.25,10.95 17.075,10.95 15.975,9.85 v1(15.95,9.85)
  Bottom Layer w0.1: R216.1@15.175,9.125 v1@16.05,10
EFR32_PC04: P200.33 P201.28 U1.5 | length 31.2
  Top Layer w0.1: U1.5@14.045,19.25 15.616,19.25 16.041,18.824 18.375,18.824 18.601,19.05 v1(19.752,19.05)
  Signal Layer 3 w0.1: v1(19.45,7.8) 19.762,8.112 19.762,9.679 19.599,9.841 19.599,14.509 ; 19.6,14.509 19.6,15.9 19.6,18.859 19.725,18.984 v1@19.725,19.05 ; v1@19.75,19.05 v1(19.752,19.05) 19.35,19.452 19.35,24.817 19.2,24.967 v1(19.2,25.45) ; v1(19.2,25.45) 19.225,25.475 v1@19.2,25.5 ; v1(19.2,25.45) v1@19.2,25.5 ; v1@19.2,25.5 19.125,25.575 19.126,25.576 19.2,25.502 v1@19.2,25.5
  Bottom Layer w0.1: v1(19.2,25.45) 19.177,25.45 v1@19.127,25.5 ; P201.28@19.445,6.45 P201.28@19.445,6.993 ; P200.33@23.255,27.55 23.255,26.955 22.5,26.2 21.7,26.2 21,25.5 v1@19.127,25.5 ; v1@19.127,25.5 19.126,25.501 19.125,25.5 v1@19.127,25.5
  Bottom Layer w0.5: P201.28@19.445,6.993 19.45,6.998 v1(19.45,7.8)
EFR32_PC05: P200.32 P201.30 U1.6 | length 32.7
  Top Layer w0.1: U1.6@13.995,19.6 14.281,19.6 14.356,19.525 15.628,19.525 16.129,19.024 16.825,19.024 16.953,19.152 17.929,19.152 v1(18.152,19.375)
  Signal Layer 3 w0.1: v1(18.152,19.375) 19.094,19.375 ; v2@19.125,26.1 19.125,26.025 18.692,25.592 18.692,25.128 19.094,24.725 19.094,19.375 ; v1(19.25,8.45) 19.25,8.859 19.399,9.008 19.399,14.501 18.75,15.15 18.75,15.475 19.35,16.075 19.35,18.328 19.094,18.584 19.094,19.375
  Bottom Layer w0.1: v2@19.225,26.1 19.6,25.725 20.65,25.725 21.35,26.425 21.35,29.2 P200.32@21.7,29.55 ; v1(19.25,8.45) 19.375,8.45 20.715,7.11 P201.30@20.715,6.45
  other v2: 19.15,26.1
EFR32_PC06: P200.30 P201.32 U1.7 | length 31.7
  Top Layer w0.1: U1.7@13.995,20 14.281,20 14.482,19.799 15.637,19.799 16.212,19.224 16.742,19.224 16.943,19.425 17.575,19.425 17.925,19.775 19.5,19.775 v1@19.775,20.05 ; v1@19.775,20.025 v1(19.8,20.025)
  Signal Layer 3 w0.1: v1@19.75,19.975 20.152,19.573 20.152,18.652 19.8,18.3 19.8,14.427 ; 19.799,14.426 19.799,10.297 20.35,9.746 v1(20.35,8.775) 20.35,8.7 v1@20.4,8.65 ; v1(19.8,20.025) 19.8,20.417 19.598,20.619 19.598,25.223 19.85,25.475 v2@19.85,26.123
  Bottom Layer w0.1: v2(19.85,26.15) 19.802,26.15 19.801,26.151 20.075,26.425 20.075,28.6 20.4,28.925 P200.30@20.4,29.65 ; v1@20.375,8.65 20.4,8.675 20.35,8.725 v1(20.35,8.775) 20.35,8.8 20.4,8.85 21.675,7.575 21.675,6.76 P201.32@21.985,6.45
EFR32_PC07: P201.34 R205.1 R208.1 U1.8 | length 23.1
  Top Layer w0.1: U1.8@14.025,20.35 14.331,20.35 14.381,20.4 v1@14.725,20.4 ; v1(14.725,20.375) v1@14.725,20.4 ; v1@14.725,20.4 14.825,20.4 14.75,20.475 14.725,20.45 v1@14.725,20.4
  Signal Layer 3 w0.1: v1(14.725,20.375) 15.925,19.175 17.3,19.175 17.85,18.625 18.175,18.625 18.85,17.95 18.85,16.225 18.25,15.625 18.25,14.3 18.575,13.975 v1(18.575,14) ; v1(22.55,14.125) 22.55,13.65 22.186,13.286 22.186,11.14 22.914,10.412 22.914,8.136 v1(23.25,7.8)
  Bottom Layer w0.1: v1(18.575,14) R205.1@19.4,14 ; R205.1@19.5,14.15 19.475,14.15 19.437,14.112 19.475,14.075 R205.1@19.45,14.05 ; R205.1@19.65,13.975 19.65,14 R208.1@21.6,14 ; R208.1@21.755,14 R208.1@21.6,14 ; v1(22.55,14.125) 21.725,14.125 R208.1@21.6,14 ; R205.1@19.4,14 19.5,14 R205.1@19.45,14.05 ; R205.1@19.4,14 R205.1@19.45,14.05 ; R205.1@19.4,14 19.375,14.025 19.425,14.075 R205.1@19.45,14.05
  Bottom Layer w0.5: v1(23.25,7.8) 23.25,6.775 P201.34@23.35,6.675
EFR32_PD00: U1.40 X2.1 | length 1.8
  Top Layer w0.1: U1.40@13.3,16.905 13.3,16.65 13.306,16.65 13.316,16.64 13.356,16.6 14.2,16.6 X2.1@14.65,16.15
EFR32_PD01: U1.39 X2.2 | length 3.1
  Top Layer w0.1: U1.39@12.9,16.905 12.9,16.619 13.134,16.385 13.765,16.385 14.05,16.1 14.05,15.25 14.35,14.95 X2.2@14.525,14.95
EFR32_PD02: P200.31 P201.17 U1.38 | length 50.6
  Top Layer w0.1: U1.38@12.5,16.905 12.511,16.894 12.511,16.631 12.49,16.61 12.826,16.274 12.941,16.274 13.043,16.171 13.282,16.171 13.478,15.976 v1(13.576,15.976)
  Signal Layer 3 w0.1: v1(13.102,2.109) 14.404,3.411 19.302,3.411 20.652,4.76 20.652,5.508 21.989,6.844 21.989,9.528 21.722,9.794 21.395,9.794 20.423,10.766 20.423,14.723 v2(20.75,15.05) ; v1(13.576,15.976) 13.599,15.976 14.7,14.875 17.052,14.875 v2(17.526,14.401) ; v1(22.175,29) 22.615,28.56 22.615,17.807 23.435,16.987 v1(23.435,15.05)
  Bottom Layer w0.1: P201.17@13.095,3.55 P201.17@13.102,3.543 ; v2(17.526,14.401) 17.826,14.401 18.35,14.925 20.148,14.925 20.273,15.05 v2(20.75,15.05) v1(23.435,15.05) ; P200.31@21.985,27.55 21.985,28.16 22.05,28.225 22.3,28.225 22.3,28.875 v1(22.175,29)
  Bottom Layer w0.2: v1(13.102,2.109) P201.17@13.102,3.543
EFR32_PD03: R218.1 R219.1 U1.37 | length 16.8
  Top Layer w0.1: U1.37@12.1,16.905 12.1,16.619 v1@12.96,15.76
  Signal Layer 3 w0.1: v1(12.976,15.776) 12.976,15.249 13.625,14.6 16.7,14.6 v2(17.525,13.775) ; v2@21.1,14.55 v2(20.976,14.426) 20.623,14.073 20.623,11.167 v1(21.529,10.262)
  Bottom Layer w0.1: v2(17.525,13.775) 17.65,13.775 18.575,14.7 20.275,14.7 20.549,14.426 v2(20.976,14.426) ; R219.1@22.315,10.262 R219.1@22.331,10.278
  Bottom Layer w0.2: v1(21.529,10.262) R219.1@22.315,10.262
